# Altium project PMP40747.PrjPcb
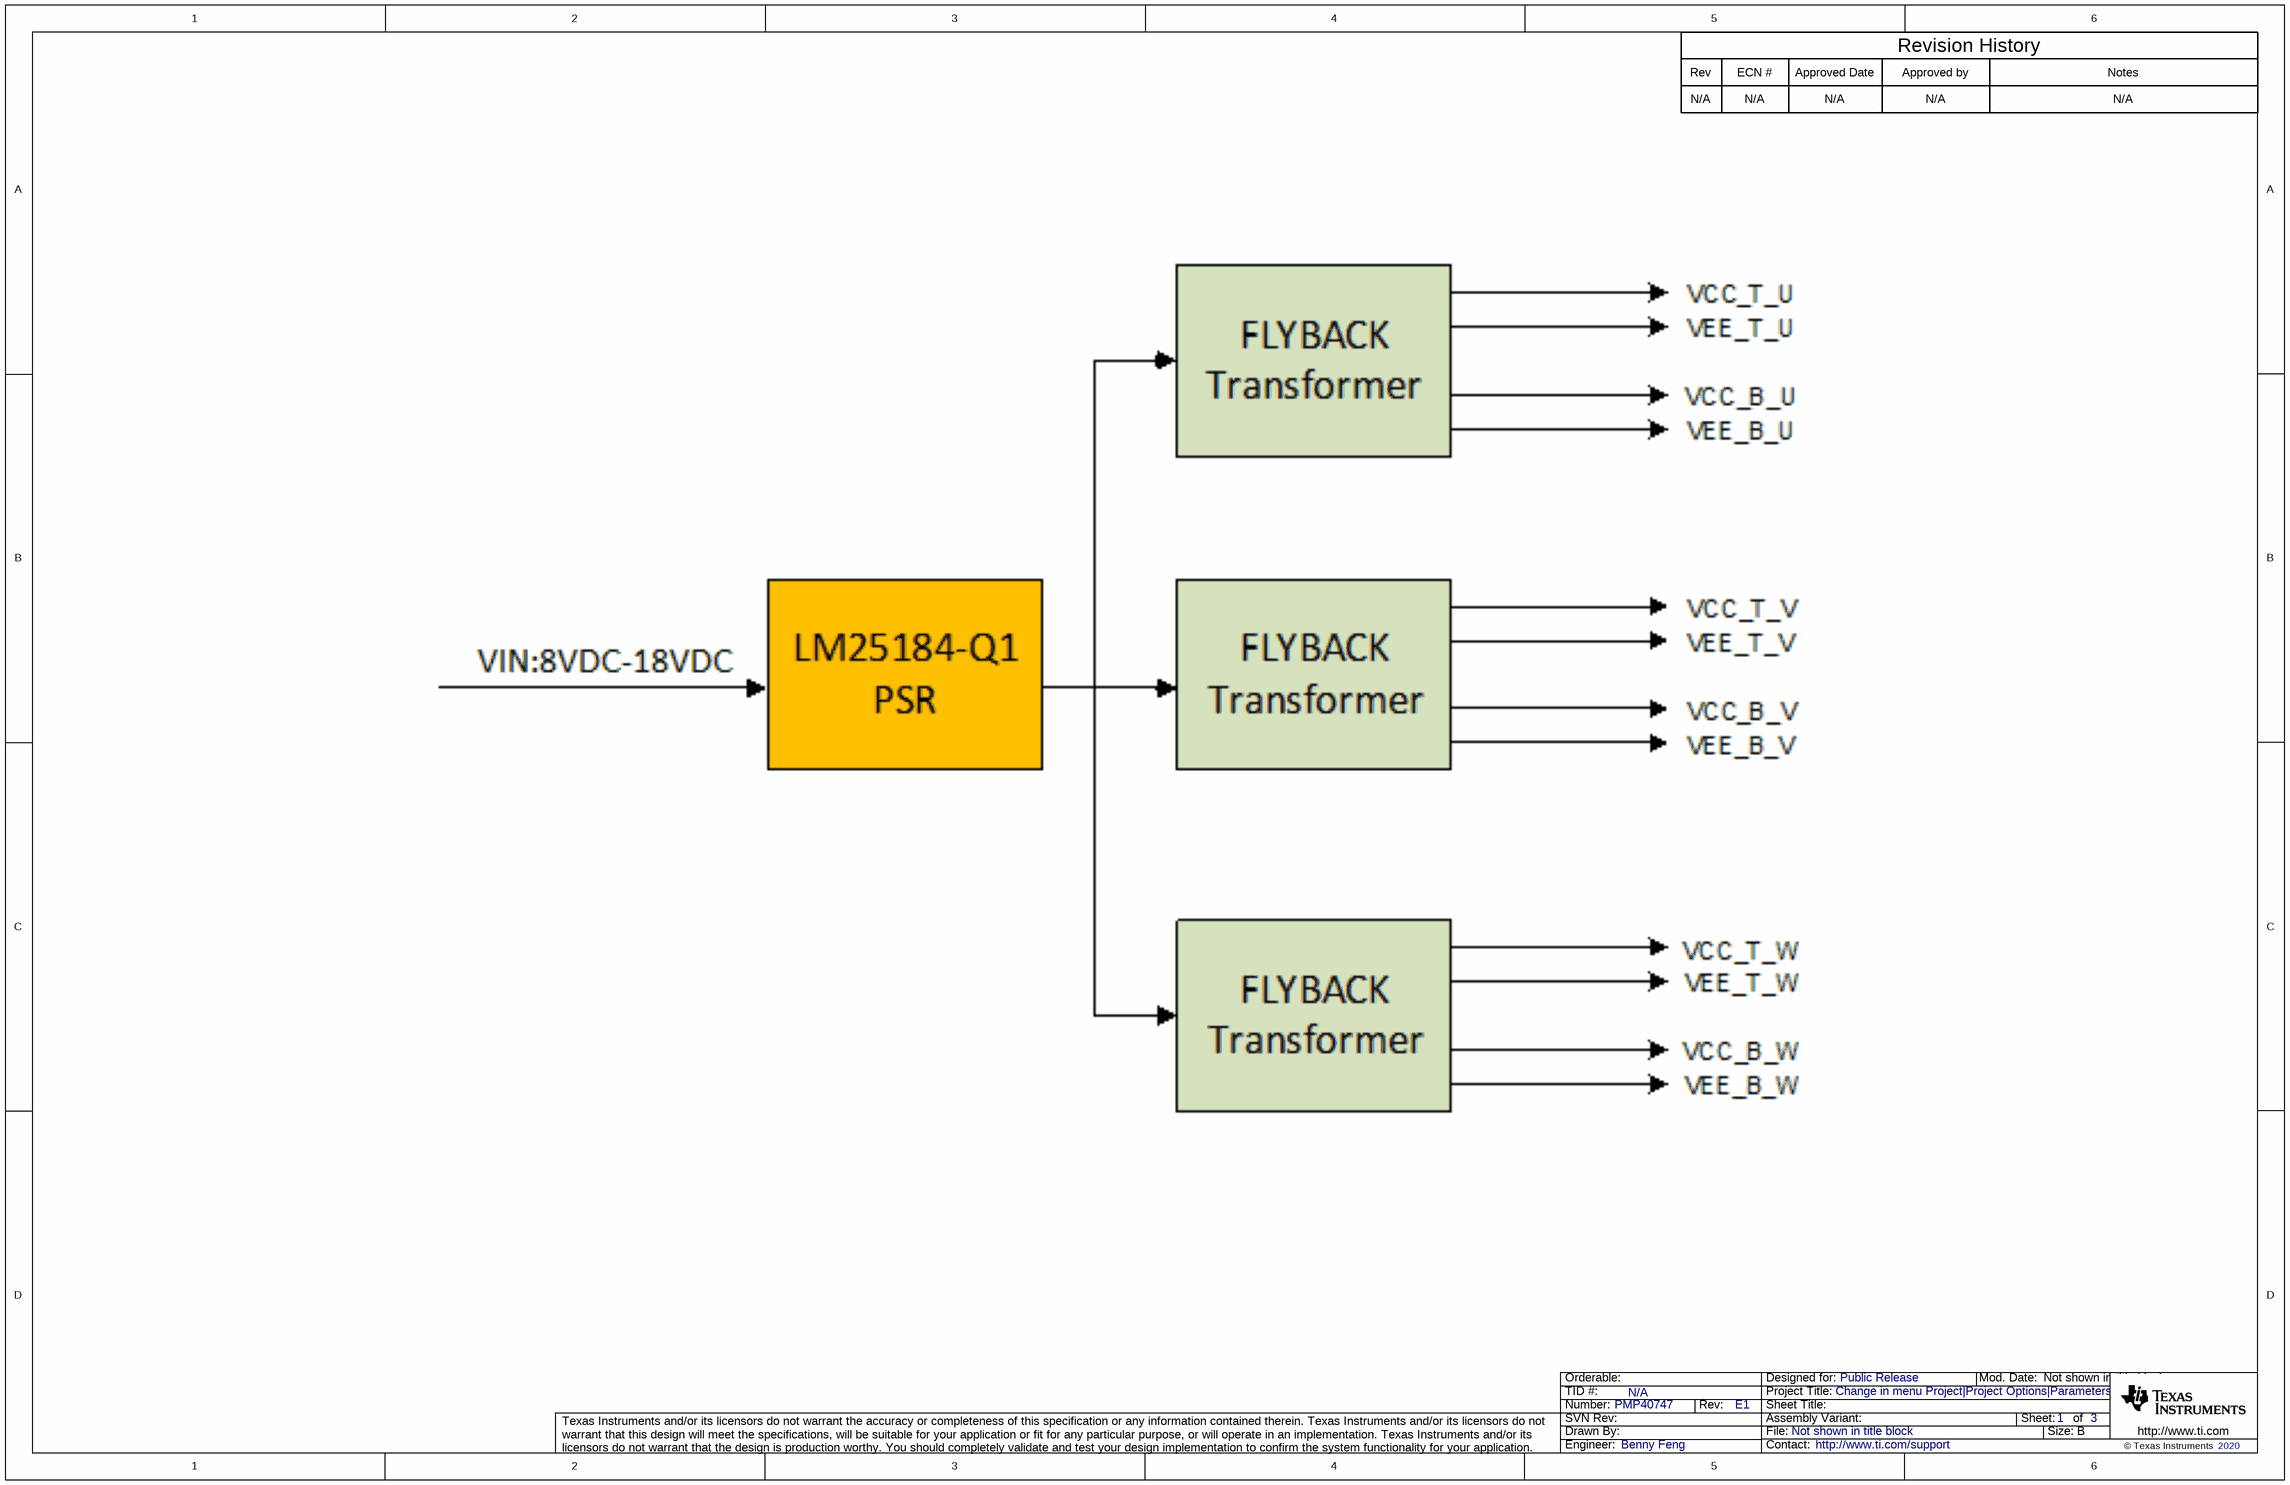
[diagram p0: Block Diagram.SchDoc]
CopyrightYear: 2020; PCB_Layout: Benny; PCB_Rev: E1; PRJ_Customer: Public Release; PRJ_Engineer: Benny Feng; PRJ_Number: PMP40747; PRJ_Title: Change in menu Project|Project Options|Parameters; SCH_Rev: E1; TechSupport: http://www.ti.com/support; TID: N/A
2 sheets, 110 parts. Net scope: global (net labels, ports and power ports of the same name join across sheets).
Board file: PMP40747PCB.PcbDoc
Sheets:
  Block Diagram.SchDoc
  PMP40747 SCH.SchDoc

## Sheet Block Diagram.SchDoc
size 431 x 279 mm; Date: Not shown in title block; ApprovedBy: Not shown in title block; CheckedBy: Not shown in title block; Author: Not shown in title block; CompanyName: Not shown in title block; Engineer: Not shown in title block; Organization: Not shown in title block; Address1: Not shown in title block; Address2: Not shown in title block; Address3: Not shown in title block; Address4: Not shown in title block; DocumentNumber: 1; Revision: Use project parameter SCH_Rev; SheetNumber: 1; SheetTotal: 3; PageSetup: Record=PageOptions¦CenterHorizontal=True¦CenterVertical=True¦PrintScale=1.00¦XCorrection=1.00¦YCorrection=1.00¦PrintKind=0¦BorderSize=5000000¦LeftOffset=0¦BottomOffset=0¦Orientation=2¦PaperLength=1000¦PaperWidth=1000¦Scale=100¦PaperSource=15¦PrintQuality=600¦MediaType=1¦DitherType=10¦PaperKind=Letter¦PrintScaleMode=1

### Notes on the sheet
- Rev
- N/A
- ECN #
- Approved Date
- Approved by
- Revision History
- Notes

## Sheet PMP40747 SCH.SchDoc
size 431 x 279 mm; Date: Not shown in title block; ApprovedBy: Not shown in title block; CheckedBy: Not shown in title block; Author: Not shown in title block; CompanyName: Not shown in title block; Engineer: Not shown in title block; Organization: Not shown in title block; Address1: Not shown in title block; Address2: Not shown in title block; Address3: Not shown in title block; Address4: Not shown in title block; DocumentNumber: 2; Revision: Use project parameter SCH_Rev; SheetNumber: 2; SheetTotal: 3; PageSetup: Record=PageOptions¦CenterHorizontal=True¦CenterVertical=True¦PrintScale=1.00¦XCorrection=1.00¦YCorrection=1.00¦PrintKind=0¦BorderSize=5000000¦LeftOffset=0¦BottomOffset=0¦Orientation=2¦PaperLength=1000¦PaperWidth=1000¦Scale=100¦PaperSource=15¦PrintQuality=600¦MediaType=1¦DitherType=10¦PaperKind=Letter¦PrintScaleMode=1
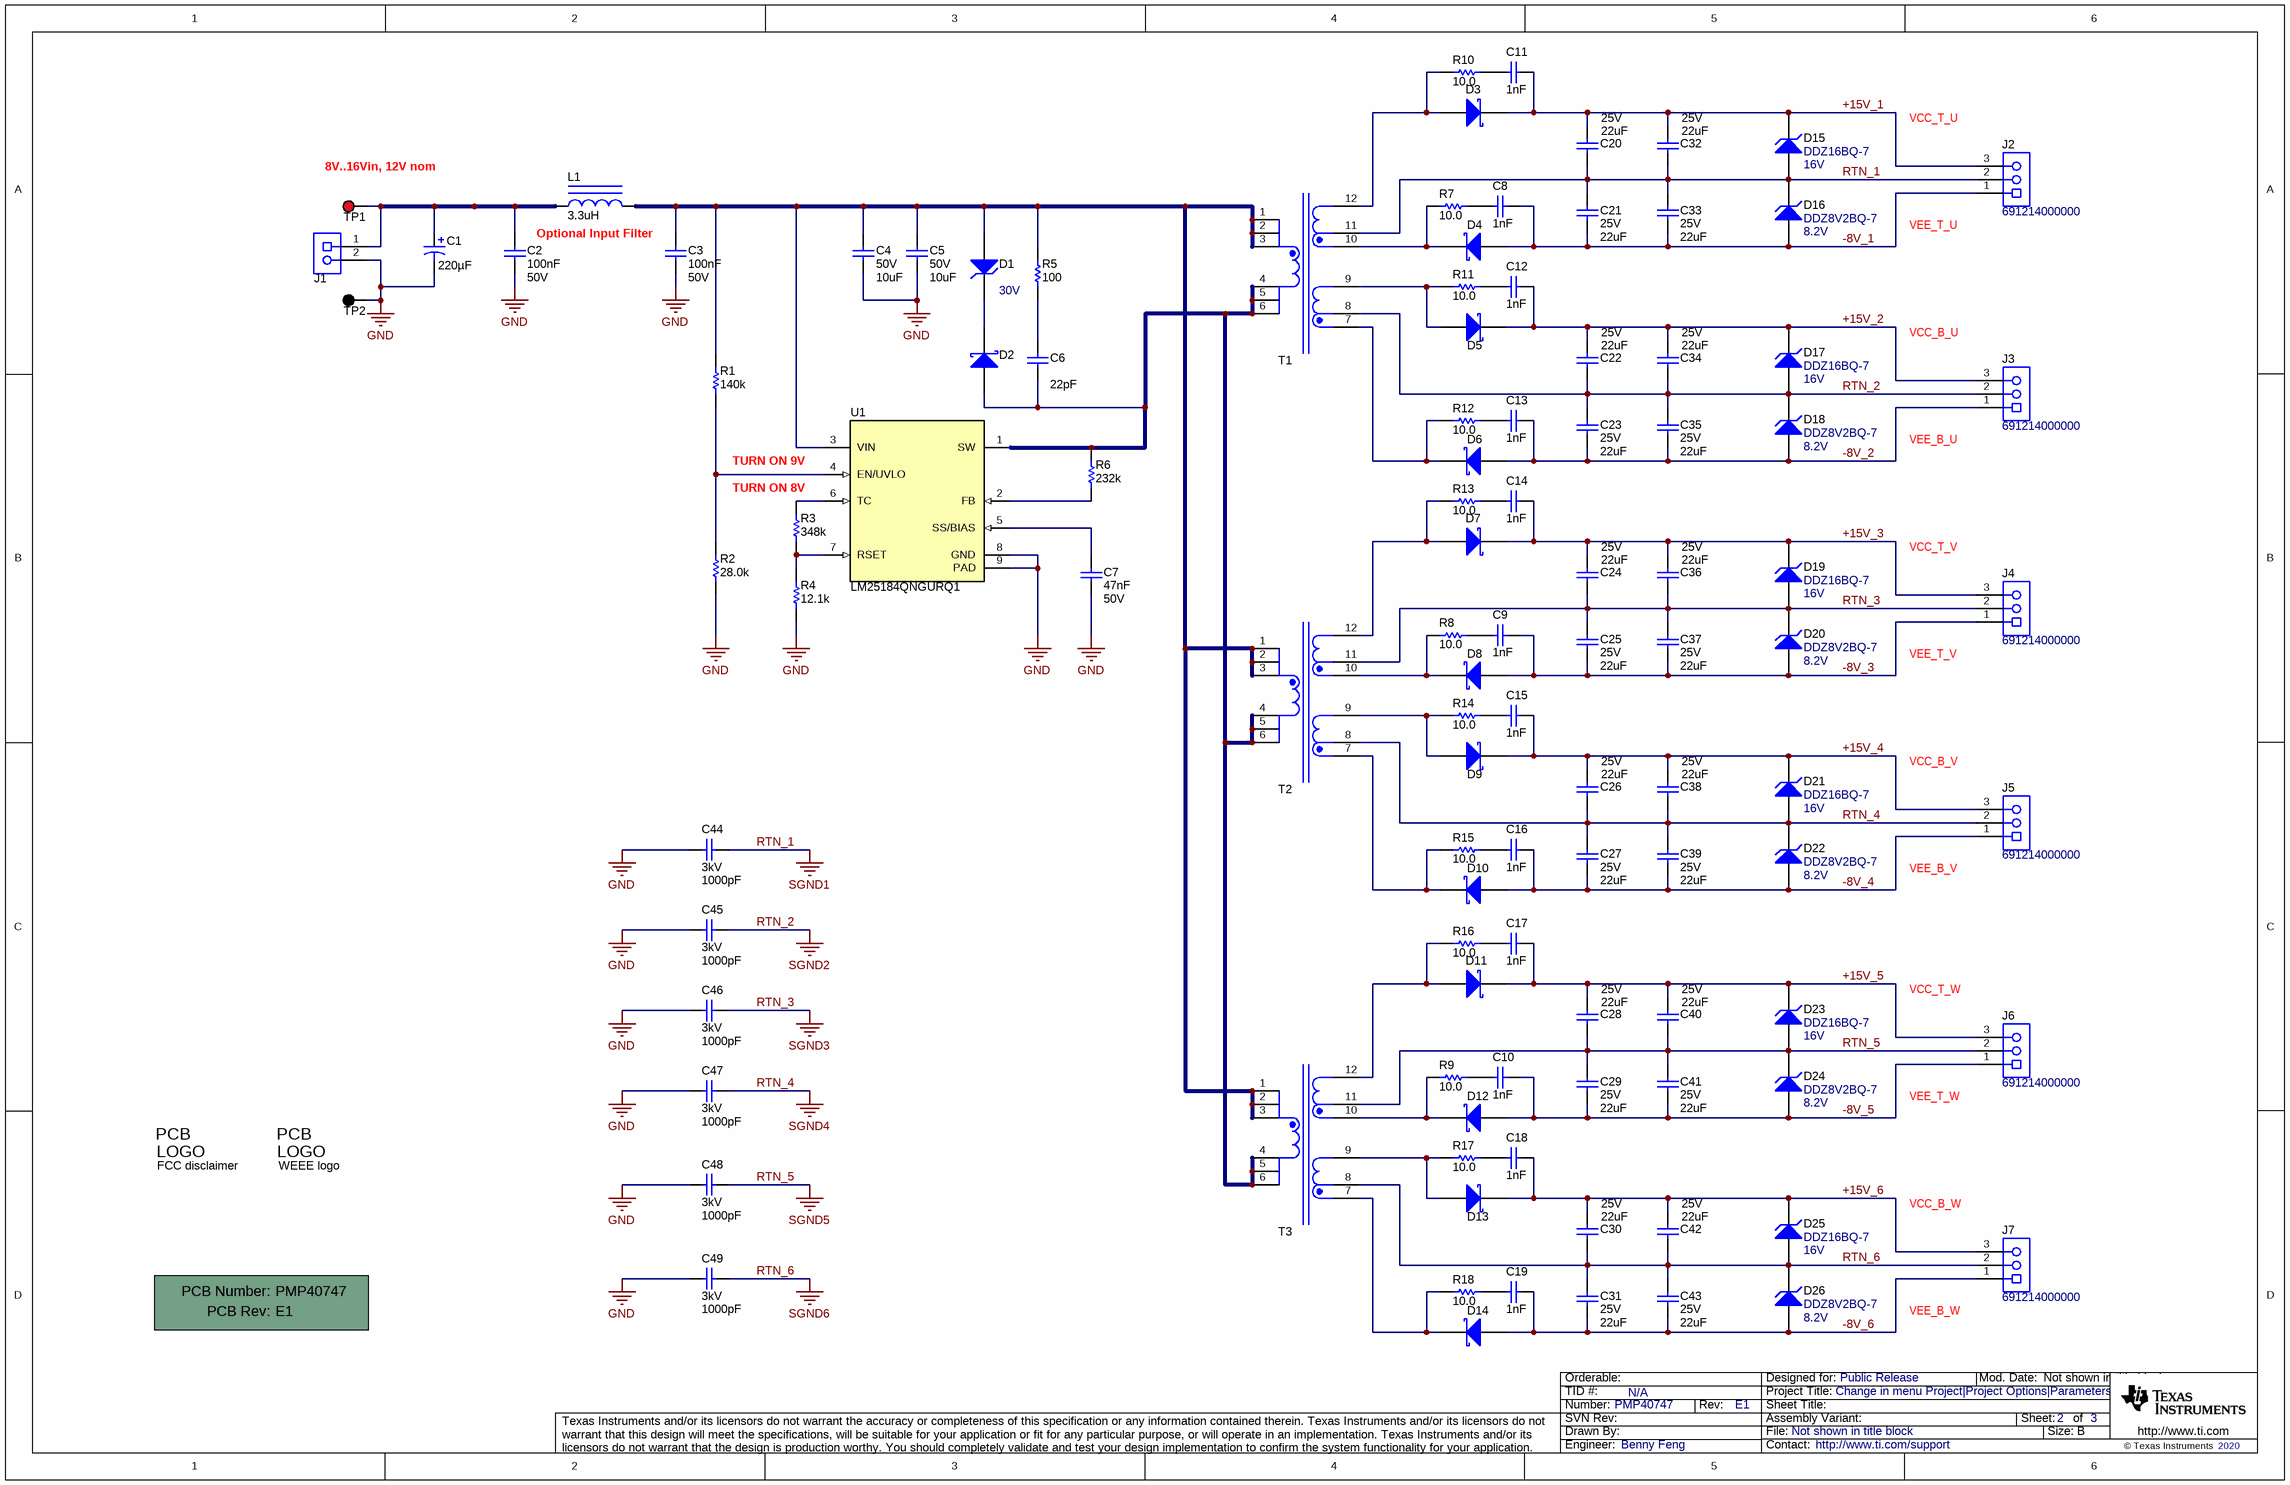
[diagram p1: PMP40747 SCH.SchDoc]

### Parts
!PCB1  Printed Circuit Board  (value not drawn)  (mechanical)
C1  ValueDisplayed: 220µF  [SM_RADIAL_F]  (hidden comment: EEE-FK1E221P)
C2  Cap_F: 100nF  VDC_V: 50V  [0603]  (hidden comment: CGA3E2X7R1H104K080AA)
C3  Cap_F: 100nF  VDC_V: 50V  [0603]  (hidden comment: CGA3E2X7R1H104K080AA)
C4  VDC_V: 50V  ValueDisplayed: 10uF  [1210_270]  (hidden comment: UMJ325KB7106KMHT)
C5  VDC_V: 50V  ValueDisplayed: 10uF  [1210_270]  (hidden comment: UMJ325KB7106KMHT)
C6  ValueDisplayed: 22pF  [0603L]  (hidden comment: AC0603JRNPOYBN220)
C7  Cap_F: 47nF  VDC_V: 50V  [0603]  (hidden comment: CGA3E2X7R1H473K080AA)
C8  Cap_F: 1nF  [0603]  (hidden comment: CGA3E2X7R2A102K080AA)
C9  Cap_F: 1nF  [0603]  (hidden comment: CGA3E2X7R2A102K080AA)
C10  Cap_F: 1nF  [0603]  (hidden comment: CGA3E2X7R2A102K080AA)
C11  Cap_F: 1nF  [0603]  (hidden comment: CGA3E2X7R2A102K080AA)
C12  Cap_F: 1nF  [0603]  (hidden comment: CGA3E2X7R2A102K080AA)
C13  Cap_F: 1nF  [0603]  (hidden comment: CGA3E2X7R2A102K080AA)
C14  Cap_F: 1nF  [0603]  (hidden comment: CGA3E2X7R2A102K080AA)
C15  Cap_F: 1nF  [0603]  (hidden comment: CGA3E2X7R2A102K080AA)
C16  Cap_F: 1nF  [0603]  (hidden comment: CGA3E2X7R2A102K080AA)
C17  Cap_F: 1nF  [0603]  (hidden comment: CGA3E2X7R2A102K080AA)
C18  Cap_F: 1nF  [0603]  (hidden comment: CGA3E2X7R2A102K080AA)
C19  Cap_F: 1nF  [0603]  (hidden comment: CGA3E2X7R2A102K080AA)
C20  VDC_V: 25V  ValueDisplayed: 22uF  [1210_270]  (hidden comment: TMK325B7226MM-PR)
C21  VDC_V: 25V  ValueDisplayed: 22uF  [1210_270]  (hidden comment: TMK325B7226MM-PR)
C22  VDC_V: 25V  ValueDisplayed: 22uF  [1210_270]  (hidden comment: TMK325B7226MM-PR)
C23  VDC_V: 25V  ValueDisplayed: 22uF  [1210_270]  (hidden comment: TMK325B7226MM-PR)
C24  VDC_V: 25V  ValueDisplayed: 22uF  [1210_270]  (hidden comment: TMK325B7226MM-PR)
C25  VDC_V: 25V  ValueDisplayed: 22uF  [1210_270]  (hidden comment: TMK325B7226MM-PR)
C26  VDC_V: 25V  ValueDisplayed: 22uF  [1210_270]  (hidden comment: TMK325B7226MM-PR)
C27  VDC_V: 25V  ValueDisplayed: 22uF  [1210_270]  (hidden comment: TMK325B7226MM-PR)
C28  VDC_V: 25V  ValueDisplayed: 22uF  [1210_270]  (hidden comment: TMK325B7226MM-PR)
C29  VDC_V: 25V  ValueDisplayed: 22uF  [1210_270]  (hidden comment: TMK325B7226MM-PR)
C30  VDC_V: 25V  ValueDisplayed: 22uF  [1210_270]  (hidden comment: TMK325B7226MM-PR)
C31  VDC_V: 25V  ValueDisplayed: 22uF  [1210_270]  (hidden comment: TMK325B7226MM-PR)
C32  VDC_V: 25V  ValueDisplayed: 22uF  [1210_270]  (hidden comment: TMK325B7226MM-PR)
C33  VDC_V: 25V  ValueDisplayed: 22uF  [1210_270]  (hidden comment: TMK325B7226MM-PR)
C34  VDC_V: 25V  ValueDisplayed: 22uF  [1210_270]  (hidden comment: TMK325B7226MM-PR)
C35  VDC_V: 25V  ValueDisplayed: 22uF  [1210_270]  (hidden comment: TMK325B7226MM-PR)
C36  VDC_V: 25V  ValueDisplayed: 22uF  [1210_270]  (hidden comment: TMK325B7226MM-PR)
C37  VDC_V: 25V  ValueDisplayed: 22uF  [1210_270]  (hidden comment: TMK325B7226MM-PR)
C38  VDC_V: 25V  ValueDisplayed: 22uF  [1210_270]  (hidden comment: TMK325B7226MM-PR)
C39  VDC_V: 25V  ValueDisplayed: 22uF  [1210_270]  (hidden comment: TMK325B7226MM-PR)
C40  VDC_V: 25V  ValueDisplayed: 22uF  [1210_270]  (hidden comment: TMK325B7226MM-PR)
C41  VDC_V: 25V  ValueDisplayed: 22uF  [1210_270]  (hidden comment: TMK325B7226MM-PR)
C42  VDC_V: 25V  ValueDisplayed: 22uF  [1210_270]  (hidden comment: TMK325B7226MM-PR)
C43  VDC_V: 25V  ValueDisplayed: 22uF  [1210_270]  (hidden comment: TMK325B7226MM-PR)
C44  VDC_V: 3kV  ValueDisplayed: 1000pF  [1812_180]  (hidden comment: C1812C102KHRACAUTO)
C45  VDC_V: 3kV  ValueDisplayed: 1000pF  [1812_180]  (hidden comment: C1812C102KHRACAUTO)
C46  VDC_V: 3kV  ValueDisplayed: 1000pF  [1812_180]  (hidden comment: C1812C102KHRACAUTO)
C47  VDC_V: 3kV  ValueDisplayed: 1000pF  [1812_180]  (hidden comment: C1812C102KHRACAUTO)
C48  VDC_V: 3kV  ValueDisplayed: 1000pF  [1812_180]  (hidden comment: C1812C102KHRACAUTO)
C49  VDC_V: 3kV  ValueDisplayed: 1000pF  [1812_180]  (hidden comment: C1812C102KHRACAUTO)
D1  value 30V  [SMA]  (hidden comment: 3SMAJ5936B-TP)
D2  PMEG60T30ELRX  [SOD-123W]  (value not drawn)
D3  PMEG6010CEH,115  [SOD-123F]  (value not drawn)
D4  PMEG6010CEH,115  [SOD-123F]  (value not drawn)
D5  PMEG6010CEH,115  [SOD-123F]  (value not drawn)
D6  PMEG6010CEH,115  [SOD-123F]  (value not drawn)
D7  PMEG6010CEH,115  [SOD-123F]  (value not drawn)
D8  PMEG6010CEH,115  [SOD-123F]  (value not drawn)
D9  PMEG6010CEH,115  [SOD-123F]  (value not drawn)
D10  PMEG6010CEH,115  [SOD-123F]  (value not drawn)
D11  PMEG6010CEH,115  [SOD-123F]  (value not drawn)
D12  PMEG6010CEH,115  [SOD-123F]  (value not drawn)
D13  PMEG6010CEH,115  [SOD-123F]  (value not drawn)
D14  PMEG6010CEH,115  [SOD-123F]  (value not drawn)
D15  DDZ16BQ-7  value 16V  [SOD-123]
D16  DDZ8V2BQ-7  value 8.2V  [SOD-123]
D17  DDZ16BQ-7  value 16V  [SOD-123]
D18  DDZ8V2BQ-7  value 8.2V  [SOD-123]
D19  DDZ16BQ-7  value 16V  [SOD-123]
D20  DDZ8V2BQ-7  value 8.2V  [SOD-123]
D21  DDZ16BQ-7  value 16V  [SOD-123]
D22  DDZ8V2BQ-7  value 8.2V  [SOD-123]
D23  DDZ16BQ-7  value 16V  [SOD-123]
D24  DDZ8V2BQ-7  value 8.2V  [SOD-123]
D25  DDZ16BQ-7  value 16V  [SOD-123]
D26  DDZ8V2BQ-7  value 8.2V  [SOD-123]
J1  ED120/2DS  [On-Shore_ED120_2DS]  (value not drawn)
J2  691214000000  [Wurth_691214110003]
J3  691214000000  [Wurth_691214110003]
J4  691214000000  [Wurth_691214110003]
J5  691214000000  [Wurth_691214110003]
J6  691214000000  [Wurth_691214110003]
J7  691214000000  [Wurth_691214110003]
L1  ValueDisplayed: 3.3uH  [XAL4030]  (hidden comment: XAL4030-332MEB)
Logo1  FCC disclaimer  [FCC_disclaimer]  (no BOM)
Logo2  WEEE logo  [WEEE_Minimum]  (no BOM)
R1  ValueDisplayed: 140k  [0603]  (hidden comment: CRCW0603140KFKEA)
R2  ValueDisplayed: 28.0k  [0603]  (hidden comment: CRCW060328K0FKEA)
R3  ValueDisplayed: 348k  [0603]  (hidden comment: CRCW0603348KFKEA)
R4  ValueDisplayed: 12.1k  [0603]  (hidden comment: CRCW060312K1FKEA)
R5  ValueDisplayed: 100  [0603L]  (hidden comment: CRCW0603100RFKEA)
R6  ValueDisplayed: 232k  [0603]  (hidden comment: CRCW0603232KFKEA)
R7  ValueDisplayed: 10.0  [0603]  (hidden comment: CRCW060310R0FKEAHP)
R8  ValueDisplayed: 10.0  [0603]  (hidden comment: CRCW060310R0FKEAHP)
R9  ValueDisplayed: 10.0  [0603]  (hidden comment: CRCW060310R0FKEAHP)
R10  ValueDisplayed: 10.0  [0603]  (hidden comment: CRCW060310R0FKEAHP)
R11  ValueDisplayed: 10.0  [0603]  (hidden comment: CRCW060310R0FKEAHP)
R12  ValueDisplayed: 10.0  [0603]  (hidden comment: CRCW060310R0FKEAHP)
R13  ValueDisplayed: 10.0  [0603]  (hidden comment: CRCW060310R0FKEAHP)
R14  ValueDisplayed: 10.0  [0603]  (hidden comment: CRCW060310R0FKEAHP)
R15  ValueDisplayed: 10.0  [0603]  (hidden comment: CRCW060310R0FKEAHP)
R16  ValueDisplayed: 10.0  [0603]  (hidden comment: CRCW060310R0FKEAHP)
R17  ValueDisplayed: 10.0  [0603]  (hidden comment: CRCW060310R0FKEAHP)
R18  ValueDisplayed: 10.0  [0603]  (hidden comment: CRCW060310R0FKEAHP)
T1  750344812  [EFD15]  (value not drawn)
T2  750344812  [EFD15]  (value not drawn)
T3  750344812  [EFD15]  (value not drawn)
TP1  5010  [Keystone5010]  (value not drawn)
TP2  5011  [Keystone5011]  (value not drawn)
U1  LM25184QNGURQ1  [NGU0008C]

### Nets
GND: C1.2(-) C2.2 C3.2 C4.2 C5.2 C7.2 C44.2 C45.2 C46.2 C47.2 C48.2 C49.2 J1.2 R2.1 R4.1 TP2.1 U1.8(GND) U1.9(PAD)
RTN_1: C20.1 C21.1 C32.1 C33.1 C44.1 D15.2(A) D16.1(K) J2.2 T1.11  [also labelled SGND1]
RTN_2: C22.1 C23.1 C34.1 C35.1 C45.1 D17.2(A) D18.1(K) J3.2 T1.8  [also labelled SGND2]
RTN_3: C24.1 C25.1 C36.1 C37.1 C46.1 D19.2(A) D20.1(K) J4.2 T2.11  [also labelled SGND3]
RTN_4: C26.1 C27.1 C38.1 C39.1 C47.1 D21.2(A) D22.1(K) J5.2 T2.8  [also labelled SGND4]
RTN_5: C28.1 C29.1 C40.1 C41.1 C48.1 D23.2(A) D24.1(K) J6.2 T3.11  [also labelled SGND5]
RTN_6: C30.1 C31.1 C42.1 C43.1 C49.1 D25.2(A) D26.1(K) J7.2 T3.8  [also labelled SGND6]
+15V_1: C11.1 C20.2 C32.2 D3.1(K) D15.1(K) J2.3
+15V_2: C12.1 C22.2 C34.2 D5.1(K) D17.1(K) J3.3
+15V_3: C14.1 C24.2 C36.2 D7.1(K) D19.1(K) J4.3
+15V_4: C15.1 C26.2 C38.2 D9.1(K) D21.1(K) J5.3
+15V_5: C17.1 C28.2 C40.2 D11.1(K) D23.1(K) J6.3
+15V_6: C18.1 C30.2 C42.2 D13.1(K) D25.1(K) J7.3
-8V_1: C8.1 C21.2 C33.2 D4.2(A) D16.2(A) J2.1
-8V_2: C13.1 C23.2 C35.2 D6.2(A) D18.2(A) J3.1
-8V_3: C9.1 C25.2 C37.2 D8.2(A) D20.2(A) J4.1
-8V_4: C16.1 C27.2 C39.2 D10.2(A) D22.2(A) J5.1
-8V_5: C10.1 C29.2 C41.2 D12.2(A) D24.2(A) J6.1
-8V_6: C19.1 C31.2 C43.2 D14.2(A) D26.2(A) J7.1
NetC1_1: C1.1(+) C2.1 J1.1 L1.1 TP1.1
NetC3_1: C3.1 C4.1 C5.1 D1.2(A) L1.2 R1.2 R5.2 T1.1 T1.2 T1.3 T2.1 T2.2 T2.3 T3.1 T3.2 T3.3 U1.3(VIN)
NetC6_1: C6.1 R5.1
NetC6_2: C6.2 D2.2(A) R6.2 T1.4 T1.5 T1.6 T2.4 T2.5 T2.6 T3.4 T3.5 T3.6 U1.1(SW)
NetC7_1: C7.1 U1.5(SS/BIAS)
NetC8_2: C8.2 R7.2
NetC9_2: C9.2 R8.2
NetC10_2: C10.2 R9.2
NetC11_2: C11.2 R10.2
NetC12_2: C12.2 R11.2
NetC13_2: C13.2 R12.2
NetC14_2: C14.2 R13.2
NetC15_2: C15.2 R14.2
NetC16_2: C16.2 R15.2
NetC17_2: C17.2 R16.2
NetC18_2: C18.2 R17.2
NetC19_2: C19.2 R18.2
NetD1_1: D1.1(K) D2.1(K)
NetD3_2: D3.2(A) R10.1 T1.12
NetD4_1: D4.1(K) R7.1 T1.10
NetD5_2: D5.2(A) R11.1 T1.9
NetD6_1: D6.1(K) R12.1 T1.7
NetD7_2: D7.2(A) R13.1 T2.12
NetD8_1: D8.1(K) R8.1 T2.10
NetD9_2: D9.2(A) R14.1 T2.9
NetD10_1: D10.1(K) R15.1 T2.7
NetD11_2: D11.2(A) R16.1 T3.12
NetD12_1: D12.1(K) R9.1 T3.10
NetD13_2: D13.2(A) R17.1 T3.9
NetD14_1: D14.1(K) R18.1 T3.7
NetR1_1: R1.1 R2.2 U1.4(EN/UVLO)
NetR3_1: R3.1 R4.2 U1.7(RSET)
NetR3_2: R3.2 U1.6(TC)
NetR6_1: R6.1 U1.2(FB)

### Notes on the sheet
- (near TP1) 8V..16Vin, 12V nom
- VCC_T_U
- Optional Input Filter
- VEE_T_U
- VCC_B_U
- TURN ON 9V
- (near R3) TURN ON 8V
- VEE_B_U
- VCC_T_V
- VEE_T_V
- VCC_B_V
- VEE_B_V
- VCC_T_W
- VEE_T_W
- VCC_B_W
- VEE_B_W

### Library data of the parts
!PCB1 = CMP-0003618-2: Manufacturer: Any; PartNumber: PMP40747
C1 = EEE-FK1E221P: CAP, AL, 220 µF, 25 V, +/- 20%, 0.16 ohm, SMD; Manufacturer: Panasonic; Polarized: Y; CompType: Capacitor; Value: 220uF; U/M: EA; Cap_F: 0.00022; Tolerance_%: 20; VDC_V: 25; Value2: 25V; ESR_ohm: 0.16; IRMS_A: 0.6; TaMin_C: -55; TaMax_C: 105; Cap_Case: F; AEC Category: Q200
C2 C3 = CMP-0007078-3: CAP, CERM, 0.1 uF, 50 V, +/- 10%, X7R, AEC-Q200 Grade 1, 0603; Manufacturer: TDK; TaMin_C: -55°C; ESR_ohm: 0.0296; Polarized: N; SizeAreaWB_mm2: 4.68; Value1: 0.0296 ohm; U/M: EA; Value: 0.1uF; TaMax_C: 125°C; SizeZ_mm: 1; SizeX_mm: 1.6; SizeY_mm: 0.8; SizeArea_mm2: 1.28; AEC Qualified: Y; IRMS_A: 971.99mA; AEC Category: Q200
C4 C5 = CMP-0009257-2: CAP, CERM, 10 uF, 50 V, +/- 10%, X7R, AEC-Q200 Grade 1, 1210; Manufacturer: Taiyo Yuden; TaMin_C: -55°C; Polarized: N; SizeAreaWB_mm2: 14.7; Value1: Unknown; U/M: EA; Value: 10uF; TaMax_C: 125°C; SizeZ_mm: 2.7; SizeX_mm: 3.2; SizeY_mm: 2.5; Cap_Case: 1210; SizeArea_mm2: 8; AEC Qualified: Y; Cap_F: 10µF; AEC Category: Q200; AEC Grade: 1
C6 = CMP-0080060-1: CAP, CERM, 22 pF, 250 V,+/- 5%, C0G/NP0, AEC-Q200 Grade 1, 0603; Manufacturer: Yageo America; TaMin_C: -55°C; Polarized: N; SizeAreaWB_mm2: 4.68; U/M: EA; Value: 22pF; TaMax_C: 125°C; SizeZ_mm: 1; SizeX_mm: 1.6; SizeY_mm: 0.8; Cap_Case: 0603; Value2: 250V; SizeArea_mm2: 1.28; AEC Qualified: Y; AEC Category: Q200
C7 = CMP-0007079-2: CAP, CERM, 0.047 uF, 50 V, +/- 10%, X7R, AEC-Q200 Grade 1, 0603; Manufacturer: TDK; TaMin_C: -55°C; ESR_ohm: 0.049007; Polarized: N; SizeAreaWB_mm2: 4.68; Value1: 0.049007 ohm; U/M: EA; TaMax_C: 125°C; SizeZ_mm: 1; SizeX_mm: 1.6; SizeY_mm: 0.8; SizeArea_mm2: 1.28; AEC Qualified: Y; IRMS_A: 767.528mA; AEC Category: Q200
C8-C19 = CMP-0007081-1: CAP, CERM, 1000 pF, 100 V, +/- 10%, X7R, AEC-Q200 Grade 1, 0603; Manufacturer: TDK; TaMin_C: -55°C; Polarized: N; SizeAreaWB_mm2: 4.68; Value1: 1.97137 ohm; U/M: EA; Value: 1000pF; TaMax_C: 125°C; SizeZ_mm: 1; SizeX_mm: 1.6; SizeY_mm: 0.8; Value2: 100V; SizeArea_mm2: 1.28; AEC Qualified: Y; AEC Category: Q200; ESR_ohm: 1.97137; IRMS_A: 305.705mA
C20-C43 = CMP-0009255-2: CAP, CERM, 22 uF, 25 V, +/- 10%, X7R, AEC-Q200 Grade 1, 1210; Manufacturer: Taiyo Yuden; TaMin_C: -55°C; Polarized: N; SizeAreaWB_mm2: 14.7; Value1: Unknown; U/M: EA; Value: 22uF; TaMax_C: 125°C; SizeZ_mm: 2.7; SizeX_mm: 3.2; SizeY_mm: 2.5; Cap_Case: 1210; SizeArea_mm2: 8; AEC Qualified: Y; Cap_F: 22µF; AEC Grade: 1; AEC Category: Q200
C44-C49 = CMP-0076765-1: CAP, CERM, 1000 pF, 3000 V,+/- 10%, X7R, 1812; Manufacturer: Kemet; Cap_F: 1nF; SizeAreaWB_mm2: 23.1; SizeArea_mm2: 14.4; AEC Qualified: N; AEC Category: Q200; Value: 1000pF; TaMax_C: 125°C; SizeZ_mm: 1.8; TaMin_C: -55°C; SizeY_mm: 3.2; Value2: 3000V; U/M: EA; SizeX_mm: 4.5; Cap_Case: 1812
D1 = CMP-0005515-1: Diode, Zener, 30 V, 3 W, SMA; Manufacturer: Micro Commercial Components; Power_W: 3W; SizeAreaWB_mm2: 37.3428; RJA_CperW: 226; U/M: EA; SizeZ_mm: 2.87; SizeX_mm: 5.59; SizeY_mm: 2.92; SizeArea_mm2: 16.3228; AEC Category: Q101
D2 = CMP-0085903-1: Diode, Schottky, 60 V, 3 A, AEC-Q101, SOD-123W; Manufacturer: Nexperia; Vr_V: 60V; Value1: 3A; TJmax_C: 175°C; Value: 60V; SizeY_mm: 1.7; SizeZ_mm: 1; Vf_V: 620mV; SizeArea_mm2: 5.95; SizeX_mm: 3.5; Value2: 0.62V; SizeAreaWB_mm2: 12.15; AEC Category: Q101; AEC Qualified: Y
D3-D14 = CMP-0028377-2: Diode, Schottky, 60 V, 1 A, SOD-123F; Manufacturer: Nexperia; Value1: 1A; Value2: 0.57V; TJmax_C: 150°C; Green_REACh: Incomplete; Vr_V: 60V; SizeY_mm: 1.6; Vf_V: 570mV; SizeArea_mm2: 5.6; AEC Category: Q101; SizeZ_mm: 1.1; SizeX_mm: 3.5; Value: 60V; Green_Lifecycle: Not Set; SizeAreaWB_mm2: 11.7
D15 D17 D19 D21 D23 D25 = CMP-0085138-1: Diode, Zener, 16 V, 500 mW, AEC-Q101, SOD-123; Manufacturer: Diodes Inc.; Value1: 0.5W; SizeZ_mm: 1.35; SizeX_mm: 3.85; SizeY_mm: 1.7; RJA_CperW: 425; Power_W: 500mW; SizeArea_mm2: 6.545; AEC Qualified: Y; SizeAreaWB_mm2: 13.095; AEC Category: Q101
D16 D18 D20 D22 D24 D26 = CMP-0085111-1: Diode, Zener, 8.2 V, 500 mW, AEC-Q101, SOD-123; Manufacturer: Diodes Inc.; RJA_CperW: 425; SizeY_mm: 1.7; SizeZ_mm: 1.35; SizeArea_mm2: 6.545; SizeAreaWB_mm2: 13.095; Power_W: 500mW; AEC Category: Q101; AEC Qualified: Y; SizeX_mm: 3.85; Value1: 0.5W
J1 = CMP-0074910-1: Terminal Block, 5.08 mm, 2x1, Brass, TH; Manufacturer: On-Shore Technology; Cert_VDE: Y; CNHeader: False; Current_A: 15A; Green_Lifecycle: Not Set; Shrouded: N; Gender: Female; Green_REACh: Incomplete; Voltage_V: 300V; Row_Count: 1; Pitch_mm: 5.08; CT: True
J2-J7 = CMP-0054824-1: Terminal Block, 3.5mm, 3x1, Tin, TH; Manufacturer: Wurth Elektronik; CNHeader: FALSE; Current_A: 10A; Gender: Female; Voltage_V: 300V; Row_Count: 1; Pitch_mm: 3.5; CT: TRUE; Cert_UL: Y
L1 = CMP-0060989-1: Inductor, Shielded, Composite, 3.3 uH, 5.5 A, 0.026 ohm, SMD; Manufacturer: Coilcraft; Isat: 5.5A @ 30% inductance drop; Irms: 6.6A @ 40C rise; Green_Lifecycle: Not Set; SizeAreaWB_mm2: 25; DCR_ohm: 0.026; Green_REACh: Incomplete; Value: 3.3uH; Imax_A: 5.5A; SizeZ_mm: 3.1; SizeX_mm: 4; SizeArea_mm2: 16; Ind_H: 3.3µH; AEC Category: Q200
Logo1 = CMP-0074847-1: FCC_disclaimer; Library Reference: Logo
Logo2 = CMP-0074769-1
R1 = CMP-0022048-4: RES, 140 k, 1%, 0.1 W, AEC-Q200 Grade 0, 0603; Manufacturer: Vishay-Dale; Power_W: 100mW; TempCo: 100 ppm/C; Value: 140k; EIA_Code: E96; SizeX_mm: 1.6; SizeY_mm: 0.8; SizeZ_mm: 1; Value2: 0.1W; SizeArea_mm2: 1.28; AEC Qualified: Y; VDC_V: 75V; AEC Category: Q200; AEC Grade: 0
R2 = CMP-0022260-4: RES, 28.0 k, 1%, 0.1 W, AEC-Q200 Grade 0, 0603; Manufacturer: Vishay-Dale; Power_W: 100mW; TempCo: 100 ppm/C; Value_Code: 28k0; Value: 28.0k; EIA_Code: E96; Res_ohm: 28k; SizeX_mm: 1.6; SizeY_mm: 0.8; SizeZ_mm: 1; Value2: 0.1W; SizeArea_mm2: 1.28; AEC Qualified: Y; VDC_V: 75V; AEC Category: Q200; AEC Grade: 0
R3 = CMP-0022344-4: RES, 348 k, 1%, 0.1 W, AEC-Q200 Grade 0, 0603; Manufacturer: Vishay-Dale; Power_W: 100mW; TempCo: 100 ppm/C; Value: 348k; EIA_Code: E96; SizeX_mm: 1.6; SizeY_mm: 0.8; SizeZ_mm: 1; Value2: 0.1W; SizeArea_mm2: 1.28; AEC Qualified: Y; VDC_V: 75V; AEC Category: Q200; AEC Grade: 0
R4 = CMP-0022030-4: RES, 12.1 k, 1%, 0.1 W, AEC-Q200 Grade 0, 0603; Manufacturer: Vishay-Dale; Power_W: 100mW; TempCo: 100 ppm/C; Value_Code: 12k1; Value: 12.1k; EIA_Code: E96; SizeX_mm: 1.6; SizeY_mm: 0.8; SizeZ_mm: 1; Value2: 0.1W; SizeArea_mm2: 1.28; AEC Qualified: Y; VDC_V: 75V; AEC Category: Q200; AEC Grade: 0
R5 = CMP-0021991-4: RES, 100, 1%, 0.1 W, AEC-Q200 Grade 0, 0603; Manufacturer: Vishay-Dale; Power_W: 100mW; TempCo: 100 ppm/C; Value_Code: 100R; Value: 100; EIA_Code: E96; SizeX_mm: 1.6; SizeY_mm: 0.8; SizeZ_mm: 1; Value2: 0.1W; SizeArea_mm2: 1.28; AEC Qualified: Y; VDC_V: 75V; AEC Category: Q200; AEC Grade: 0
R6 = CMP-0022224-4: RES, 232 k, 1%, 0.1 W, AEC-Q200 Grade 0, 0603; Manufacturer: Vishay-Dale; Power_W: 100mW; TempCo: 100 ppm/C; Value: 232k; EIA_Code: E96; SizeX_mm: 1.6; SizeY_mm: 0.8; SizeZ_mm: 1; Value2: 0.1W; SizeArea_mm2: 1.28; AEC Qualified: Y; VDC_V: 75V; AEC Category: Q200; AEC Grade: 0
R7-R18 = CMP-0022004-4: RES, 10.0, 1%, 0.25 W, AEC-Q200 Grade 0, 0603; Manufacturer: Vishay-Dale; Power_W: 250mW; TempCo: 100 ppm/C; Value_Code: 10R0; Value: 10.0; EIA_Code: E96; Res_ohm: 10; SizeX_mm: 1.6; SizeY_mm: 0.8; SizeZ_mm: 1; Value2: 0.25W; SizeArea_mm2: 1.28; AEC Qualified: Y; VDC_V: 75V; AEC Category: Q200; AEC Grade: 0
T1-T3 = PMP40747: Transformer, 45uH, SMT; Manufacturer: Wurth; SymbolCreator: Altium; DCR_ohm: 0.028; Lp: 45E-6; LeakageInd_H: 45E-8
TP1 = CMP-0055147-1: Test Point, Multipurpose, Red, TH; Manufacturer: Keystone; CNHeader: FALSE; Green_Lifecycle: Active; Green_REACh: Passed; ContactFinish: Silver; CT: TRUE
TP2 = CMP-0055148-1: Test Point, Multipurpose, Black, TH; Manufacturer: Keystone; CNHeader: FALSE; Green_Lifecycle: Active; Green_REACh: Passed; ContactFinish: Silver; CT: TRUE
U1 = CMP-0860959-2: 42-VIN PSR Flyback DC/DC Converter with 65-V, 4-A Integrated MOSFET, NGU0008C (WSON-8); Alternate Manufacturer: Texas Instruments; SizeAreaWB_mm2: 25; SizeZ_mm: 0.8; SizeX_mm: 4; SizeArea_mm2: 16; CompType: IC; AEC Qualified: Y; AEC Category: Q200

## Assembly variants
001: not fitted C6 C8 C9 C10 C11 C12 C13 C14 C15 C16 C17 C18 C19 D15 D16 D17 D18 D19 D20 D21 D22 D23 D24 D25 D26 R5 R7 R8 R9 R10 R11 R12 R13 R14 R15 R16 R17 R18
